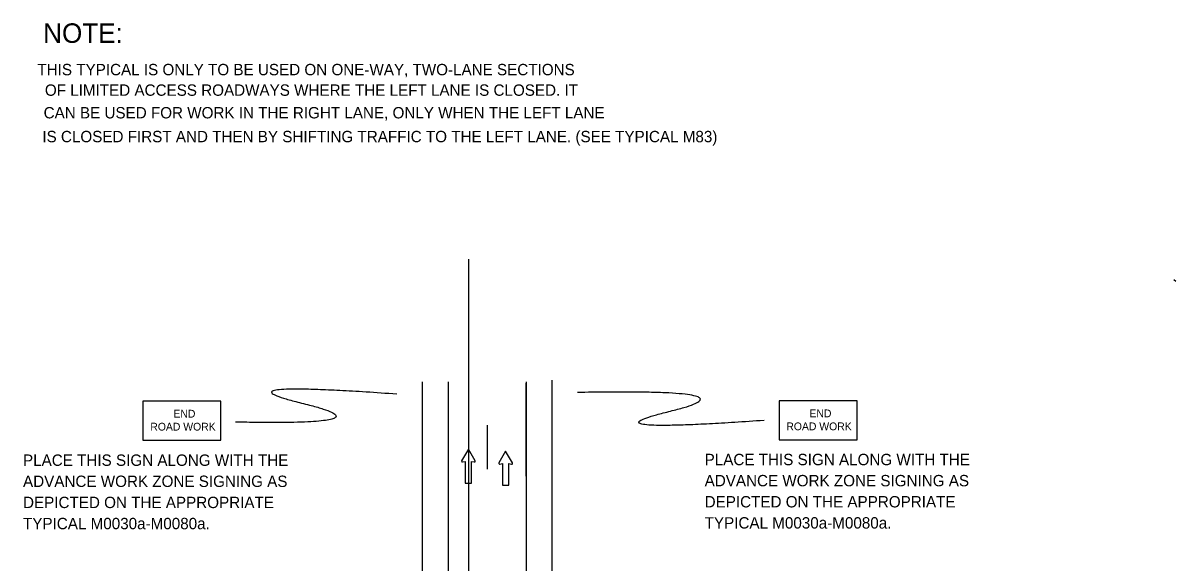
# Model space of a CAD drawing. Extents: x 15273 to 18137, y 1908 to 6555.
# Drawn here: x 15307 to 16017, y 3051 to 3383 of the extents above; entities that cross this region are included whole.
import ezdxf

# ---------------------------------------------------------------- set-up
doc = ezdxf.new("R2010")
doc.units = 0
for name, color, linetype in [('ALI_LEGAL_EX', 7, 'Continuous'), ('MT_SCRATCH_LEVEL_E', 7, 'Continuous'), ('PAVT_EDGE_EX', 7, 'Continuous'), ('TRAFFIC_SIGNS_PR', 7, 'Continuous'), ('TYPICAL_TEXT_DIMEN_EX', 7, 'Continuous'), ('TYPICAL_TEXT_DIMEN_PR', 7, 'Continuous')]:
    doc.layers.add(name, color=color, linetype=linetype)

msp = doc.modelspace()

# ---------------------------------------------------------------- linework, layer by layer
at = {"layer": 'ALI_LEGAL_EX'}
msp.add_line((15581.68, 3237.79), (15581.68, 2408.6), dxfattribs=at)
msp.add_lwpolyline([(15593.04, 3135.48), (15593.04, 3108.47)], dxfattribs=at)
at = {"layer": 'MT_SCRATCH_LEVEL_E'}
for p, q in [((15581.51, 3120.83), (15577.39, 3113.59)), ((15585.65, 3113.59), (15581.51, 3120.83)), ((15604.48, 3119.56), (15600.37, 3112.32)), ((15608.63, 3112.32), (15604.48, 3119.56)), ((15577.88, 3112.91), (15579.65, 3113.22)), ((15579.65, 3113.22), (15579.65, 3099.97)), ((15583.4, 3099.97), (15583.4, 3113.22)), ((15583.4, 3113.22), (15585.17, 3112.91)), ((15600.85, 3111.64), (15602.63, 3111.95)), ((15602.63, 3111.95), (15602.63, 3098.7)), ((15606.37, 3098.7), (15606.37, 3111.95)), ((15606.37, 3111.95), (15608.15, 3111.64)), ((15579.65, 3099.97), (15583.4, 3099.97)), ((15602.63, 3098.7), (15606.37, 3098.7))]:
    msp.add_line(p, q, dxfattribs=at)
for centre, start, end in [((15577.8, 3113.37), 150.42484, 279.96381), ((15585.24, 3113.37), 260.03619, 29.77312), ((15600.78, 3112.1), 150.42484, 279.96381), ((15608.22, 3112.1), 260.03619, 29.77312)]:
    msp.add_arc(centre, 0.463, start, end, dxfattribs=at)
at = {"layer": 'PAVT_EDGE_EX'}
for p, q in [((15553, 3162.29), (15553, 2478.74)), ((15569, 3162.29), (15569, 2478.74)), ((15617, 3162.29), (15617, 2478.74)), ((15617, 3136.16), (15617, 3161.36)), ((15633, 3163.21), (15633, 2478.74)), ((15617, 3104.11), (15617, 3136.16))]:
    msp.add_line(p, q, dxfattribs=at)
at = {"layer": 'TRAFFIC_SIGNS_PR'}
for points in [[(15381.2, 3126.32), (15429.2, 3126.32), (15429.2, 3150.32), (15381.2, 3150.32)], [(15772.77, 3126.51), (15820.77, 3126.51), (15820.77, 3150.51), (15772.77, 3150.51)]]:
    msp.add_lwpolyline(points, close=True, dxfattribs=at)
for points in [[(15537.43, 3154.66), (15422.21, 3162.89), (15536.11, 3135.31), (15438.17, 3137.48)], [(15763.57, 3138.5), (15648.35, 3130.27), (15762.26, 3157.85), (15648.8, 3155.68)]]:
    msp.add_open_spline(points, degree=2, dxfattribs=at)
at = {"layer": 'TYPICAL_TEXT_DIMEN_PR'}
msp.add_line((16015.78, 3225.17), (16017.12, 3224.27), dxfattribs=at)

# ---------------------------------------------------------------- texts
at = {"layer": 'TRAFFIC_SIGNS_PR'}
for s, height, p in [('END', 4.789, (15399.96, 3140.23)), ('END', 4.789, (15791.52, 3140.43)), ('ROAD WORK', 4.789, (15385.72, 3132.25)), ('ROAD WORK', 4.789, (15777.28, 3132.44)), ('PLACE THIS SIGN ALONG WITH THE', 7, (15307.36, 3110.53)), ('PLACE THIS SIGN ALONG WITH THE', 7, (15726.97, 3110.94)), ('ADVANCE WORK ZONE SIGNING AS', 7, (15307.36, 3097.53)), ('ADVANCE WORK ZONE SIGNING AS', 7, (15726.97, 3097.94)), ('DEPICTED ON THE APPROPRIATE', 7, (15307.36, 3084.53)), ('DEPICTED ON THE APPROPRIATE', 7, (15726.97, 3084.94)), ('TYPICAL M0030a-M0080a.', 7, (15307.36, 3071.53)), ('TYPICAL M0030a-M0080a.', 7, (15726.97, 3071.94))]:
    msp.add_text(s, height=height, dxfattribs=at).set_placement(p)
at = {"layer": 'TYPICAL_TEXT_DIMEN_EX'}
msp.add_text('NOTE:', height=12, dxfattribs=at).set_placement((15319.77, 3370.89))
at = {"layer": 'TYPICAL_TEXT_DIMEN_PR'}
for s, p in [(' THIS TYPICAL IS ONLY TO BE USED ON ONE-WAY, TWO-LANE SECTIONS', (15313.61, 3350.94)), ('OF LIMITED ACCESS ROADWAYS WHERE THE LEFT LANE IS CLOSED. IT', (15320.82, 3338.3)), ('CAN BE USED FOR WORK IN THE RIGHT LANE, ONLY WHEN THE LEFT LANE ', (15320.04, 3324.38)), ('IS CLOSED FIRST AND THEN BY SHIFTING TRAFFIC TO THE LEFT LANE. (SEE TYPICAL M83)', (15319.26, 3309.72))]:
    msp.add_text(s, height=7, dxfattribs=at).set_placement(p)

doc.saveas('drawing.dxf')
